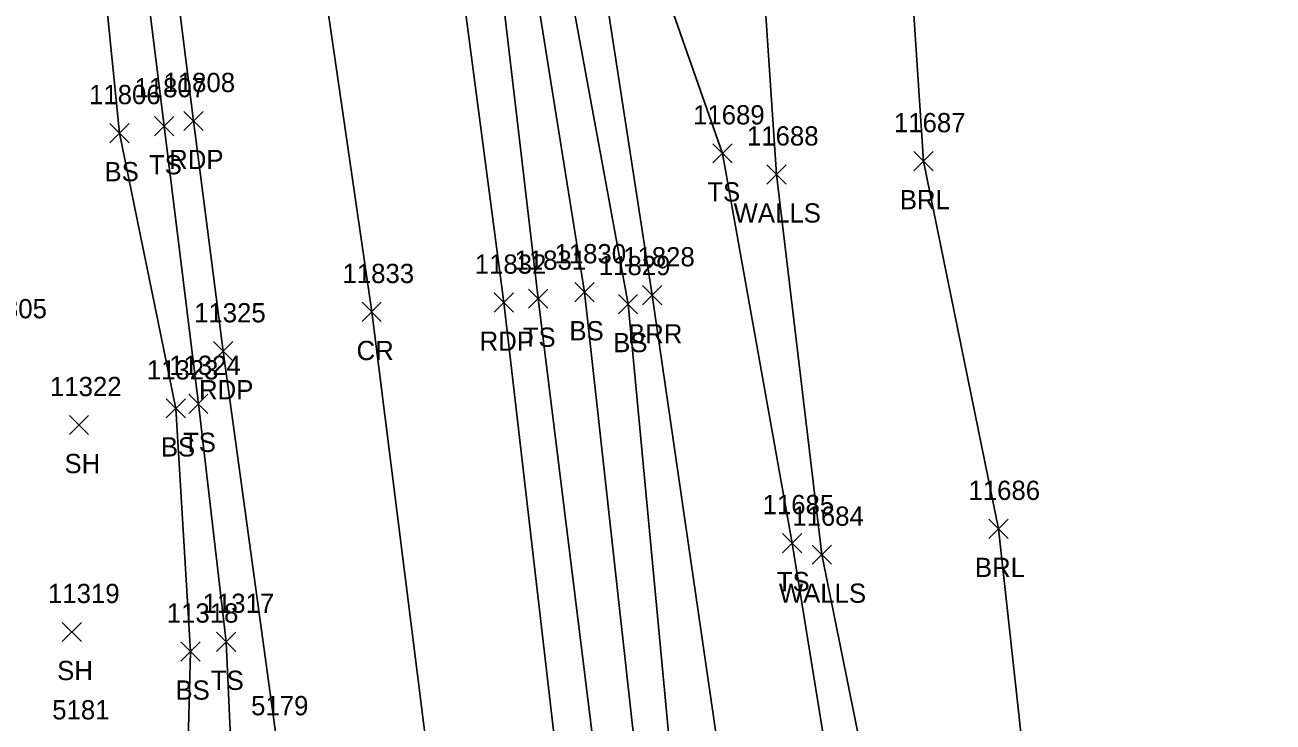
# Model space of a CAD drawing. Extents: x 1439173 to 1457902, y 641926 to 659889.
# Drawn here: x 1447904.7 to 1448034.3, y 648553.4 to 648625.8 of the extents above; entities that cross this region are included whole.
import ezdxf

# ---------------------------------------------------------------- set-up
doc = ezdxf.new("R2010")
doc.units = 0
for name, color, linetype in [('L_A', 7, 'Continuous'), ('L_I', 7, 'Continuous'), ('L_TIC', 7, 'Continuous'), ('LABL', 7, 'Continuous'), ('LELB', 7, 'Continuous'), ('LWS', 7, 'Continuous'), ('P_A', 7, 'Continuous'), ('P_I', 7, 'Continuous'), ('P_TIC', 7, 'Continuous'), ('PET', 7, 'Continuous'), ('PRC', 7, 'Continuous')]:
    doc.layers.add(name, color=color, linetype=linetype)

msp = doc.modelspace()

# ---------------------------------------------------------------- linework, layer by layer
at = {"layer": 'L_TIC'}
for points in [[(1447913.48, 648613.57), (1447915.48, 648615.57)], [(1447915.48, 648613.57), (1447913.48, 648615.57)], [(1447918.13, 648614.29), (1447920.13, 648616.29)], [(1447920.13, 648614.29), (1447918.13, 648616.29)], [(1447976.11, 648611.47), (1447978.11, 648613.47)], [(1447978.11, 648611.47), (1447976.11, 648613.47)], [(1447996.97, 648610.66), (1447998.97, 648612.66)], [(1447998.97, 648610.66), (1447996.97, 648612.66)], [(1447981.71, 648609.28), (1447983.71, 648611.28)], [(1447983.71, 648609.28), (1447981.71, 648611.28)], [(1447961.76, 648597.05), (1447963.76, 648599.05)], [(1447963.76, 648597.05), (1447961.76, 648599.05)], [(1447968.8, 648596.73), (1447970.8, 648598.73)], [(1447970.8, 648596.73), (1447968.8, 648598.73)], [(1447956.95, 648596.38), (1447958.95, 648598.38)], [(1447958.95, 648596.38), (1447956.95, 648598.38)], [(1447966.29, 648595.82), (1447968.29, 648597.82)], [(1447968.29, 648595.82), (1447966.29, 648597.82)], [(1447919.34, 648584.99), (1447921.34, 648586.99)], [(1447921.34, 648584.99), (1447919.34, 648586.99)], [(1447921.67, 648585.46), (1447923.67, 648587.46)], [(1447923.67, 648585.46), (1447921.67, 648587.46)], [(1447909.28, 648583.26), (1447911.28, 648585.26)], [(1447911.28, 648583.26), (1447909.28, 648585.26)], [(1448004.77, 648572.48), (1448006.77, 648574.48)], [(1448006.77, 648572.48), (1448004.77, 648574.48)], [(1447983.33, 648571), (1447985.33, 648573)], [(1447985.33, 648571), (1447983.33, 648573)], [(1447986.41, 648569.8), (1447988.41, 648571.8)], [(1447988.41, 648569.8), (1447986.41, 648571.8)], [(1447908.52, 648561.77), (1447910.52, 648563.77)], [(1447910.52, 648561.77), (1447908.52, 648563.77)], [(1447924.57, 648560.75), (1447926.57, 648562.75)], [(1447926.57, 648560.75), (1447924.57, 648562.75)], [(1447920.85, 648559.74), (1447922.85, 648561.74)], [(1447922.85, 648559.74), (1447920.85, 648561.74)]]:
    msp.add_lwpolyline(points, dxfattribs=at)
at = {"layer": 'LABL'}
for points in [[(1447979.13, 648514.69), (1447981.23, 648503.4), (1447992.5, 648494.26), (1448009.81, 648487.44), (1448045.94, 648493), (1448048.9, 648506.29), (1448012.47, 648506.76), (1448011.17, 648524.23), (1448005.77, 648573.48), (1447997.97, 648611.66), (1447994.73, 648661.06), (1447977.96, 648680.95), (1447960.54, 648673.52)], [(1447979.13, 648514.69), (1447977.26, 648546.38), (1447969.8, 648597.73), (1447962.02, 648648.27), (1447960.54, 648673.52)]]:
    msp.add_lwpolyline(points, dxfattribs=at)
at = {"layer": 'LELB'}
for points in [[(1447974.79, 648514.27), (1447972.12, 648545.7), (1447967.29, 648596.82), (1447958.07, 648647.1), (1447953.07, 648690.28), (1447946.6, 648739.03), (1447940.66, 648780.96), (1447936.37, 648827.1), (1447928.59, 648872.23), (1447920.72, 648916.47), (1447916.19, 648958.02), (1447909.98, 648994.25), (1447909.19, 648998.29), (1447909.54, 649003.59), (1447916.36, 649010.63), (1447924.3, 649013.7), (1447944.43, 649018.61)], [(1447969.85, 648514.47), (1447964.49, 648544.65), (1447957.95, 648597.38), (1447952.29, 648645.71), (1447946.98, 648689.75), (1447940.5, 648738.3), (1447934.59, 648780.28), (1447929.04, 648824.88), (1447922.4, 648871.3), (1447916.32, 648916.62), (1447909.85, 648957.42), (1447904.84, 648993.23), (1447904.91, 648998.9), (1447906.94, 649001.32), (1447909.54, 649003.59), (1447912.95, 649002.53)], [(1447971.97, 648514.34), (1447968.59, 648545.51), (1447962.76, 648598.05), (1447955.08, 648646.1), (1447949.31, 648689.51), (1447943.88, 648738.57), (1447940.65, 648781.02), (1447931.82, 648826.68), (1447925.82, 648871.76), (1447918.72, 648916.18), (1447912.39, 648957.17), (1447907.99, 648993.99), (1447906.16, 648998.51), (1447906.81, 648999.55), (1447907.58, 648999.87), (1447909.19, 648998.29)], [(1447857.92, 648532.04), (1447874.33, 648528.1), (1447893.57, 648529.78), (1447914.68, 648536.88), (1447921.41, 648543.42), (1447921.85, 648560.74), (1447920.34, 648585.99), (1447914.48, 648614.57), (1447909.22, 648666.97), (1447905.3, 648694.72), (1447898.39, 648708.6)], [(1447874.33, 648528.1), (1447895.68, 648524.62), (1447912.89, 648527.69), (1447920.24, 648531.8), (1447926.49, 648541.09), (1447925.57, 648561.75), (1447922.67, 648586.46), (1447919.13, 648615.29), (1447912.37, 648669.65), (1447909.66, 648697.05)], [(1447985.24, 648516.19), (1447988.97, 648543.38), (1447984.33, 648572), (1447977.11, 648612.47), (1447965.77, 648644.74), (1447960.54, 648673.52), (1447957.48, 648693.42)]]:
    msp.add_lwpolyline(points, dxfattribs=at)
at = {"layer": 'LWS'}
msp.add_lwpolyline([(1447995.63, 648530.22), (1447987.41, 648570.8), (1447982.71, 648610.28), (1447977.96, 648680.95), (1447969.02, 648732.44), (1447965.97, 648777.26), (1447965.56, 648784.62), (1447961.57, 648816.89), (1447953.14, 648865.36), (1447946.25, 648895.81)], dxfattribs=at)
at = {"layer": 'P_TIC'}
for points in [[(1447921.16, 648614.83), (1447923.16, 648616.83)], [(1447923.16, 648614.83), (1447921.16, 648616.83)], [(1447953.4, 648595.97), (1447955.4, 648597.97)], [(1447955.4, 648595.97), (1447953.4, 648597.97)], [(1447939.67, 648595), (1447941.67, 648597)], [(1447941.67, 648595), (1447939.67, 648597)], [(1447924.25, 648590.92), (1447926.25, 648592.92)], [(1447926.25, 648590.92), (1447924.25, 648592.92)]]:
    msp.add_lwpolyline(points, dxfattribs=at)
at = {"layer": 'PET'}
for points in [[(1447985.99, 648352.77), (1447984.12, 648388.61), (1447978.58, 648406.37), (1447976.75, 648417.49), (1447970.56, 648463.48), (1447964.44, 648514.86), (1447960.48, 648544.49), (1447954.4, 648596.97), (1447948.04, 648645.35), (1447942.48, 648689.3), (1447936.15, 648737.63), (1447930.52, 648780.21), (1447924.61, 648825.68), (1447919.43, 648871), (1447912.62, 648916.56), (1447907.24, 648956.8), (1447902.54, 648992.52), (1447895.42, 649044.11)], [(1447925.25, 648591.92), (1447922.16, 648615.83), (1447915.4, 648669.98), (1447912.01, 648697.18)], [(1447925.25, 648591.92), (1447930.85, 648551.12)]]:
    msp.add_lwpolyline(points, dxfattribs=at)
at = {"layer": 'PRC'}
msp.add_lwpolyline([(1448032.33, 647961.7), (1448025.03, 648003.46), (1448015.67, 648063.56), (1448008.21, 648110.03), (1448001.08, 648156.37), (1447993.04, 648207.4), (1447985.4, 648256.52), (1447977.63, 648310.23), (1447970.83, 648357.73), (1447966.46, 648396.63), (1447963.75, 648410.58), (1447956.84, 648463.17), (1447947.44, 648542.38), (1447940.67, 648596), (1447933.63, 648644.51), (1447928.19, 648688.31), (1447922.05, 648736.93), (1447916.64, 648778.15)], dxfattribs=at)

# ---------------------------------------------------------------- texts
at = {"layer": 'L_A'}
for s, p in [('BS', (1447912.92, 648609.57)), ('TS', (1447917.54, 648610.29)), ('TS', (1447975.52, 648607.47)), ('BRL', (1447995.51, 648606.66)), ('WALLS', (1447978.25, 648605.28)), ('BS', (1447961.2, 648593.05)), ('BRR', (1447967.29, 648592.73)), ('TS', (1447956.36, 648592.38)), ('BS', (1447965.74, 648591.82)), ('TS', (1447921.08, 648581.46)), ('BS', (1447918.78, 648580.99)), ('SH', (1447908.77, 648579.26)), ('BRL', (1448003.31, 648568.48)), ('TS', (1447982.74, 648567)), ('WALLS', (1447982.95, 648565.8)), ('SH', (1447908.01, 648557.77)), ('TS', (1447923.97, 648556.75)), ('BS', (1447920.29, 648555.74))]:
    msp.add_text(s, height=2, dxfattribs=at).set_placement(p)
at = {"layer": 'L_I'}
for s, p in [('11806', (1447911.32, 648617.57)), ('11807', (1447916.03, 648618.29)), ('11689', (1447974.04, 648615.47)), ('11687', (1447994.9, 648614.66)), ('11688', (1447979.64, 648613.28)), ('11830', (1447959.65, 648601.05)), ('11828', (1447966.78, 648600.73)), ('11831', (1447955.5, 648600.38)), ('11829', (1447964.26, 648599.82)), ('11805', (1447899.51, 648595.34)), ('11805', (1447899.51, 648595.34)), ('11323', (1447917.32, 648588.99)), ('11324', (1447919.65, 648589.46)), ('11322', (1447907.26, 648587.26)), ('11686', (1448002.64, 648576.48)), ('11685', (1447981.26, 648575)), ('11684', (1447984.34, 648573.8)), ('11319', (1447907.06, 648565.77)), ('11317', (1447923.11, 648564.75)), ('11318', (1447919.39, 648563.74)), ('5181', (1447907.5, 648553.69))]:
    msp.add_text(s, height=2, dxfattribs=at).set_placement(p)
at = {"layer": 'P_A'}
for s, p in [('RDP', (1447919.64, 648610.83)), ('RDP', (1447951.88, 648591.97)), ('CR', (1447939.1, 648591)), ('RDP', (1447922.74, 648586.92))]:
    msp.add_text(s, height=2, dxfattribs=at).set_placement(p)
at = {"layer": 'P_I'}
for s, p in [('11808', (1447919.05, 648618.83)), ('11832', (1447951.37, 648599.97)), ('11833', (1447937.64, 648599)), ('11325', (1447922.23, 648594.92)), ('5179', (1447928.15, 648554.12))]:
    msp.add_text(s, height=2, dxfattribs=at).set_placement(p)

doc.saveas('drawing.dxf')
